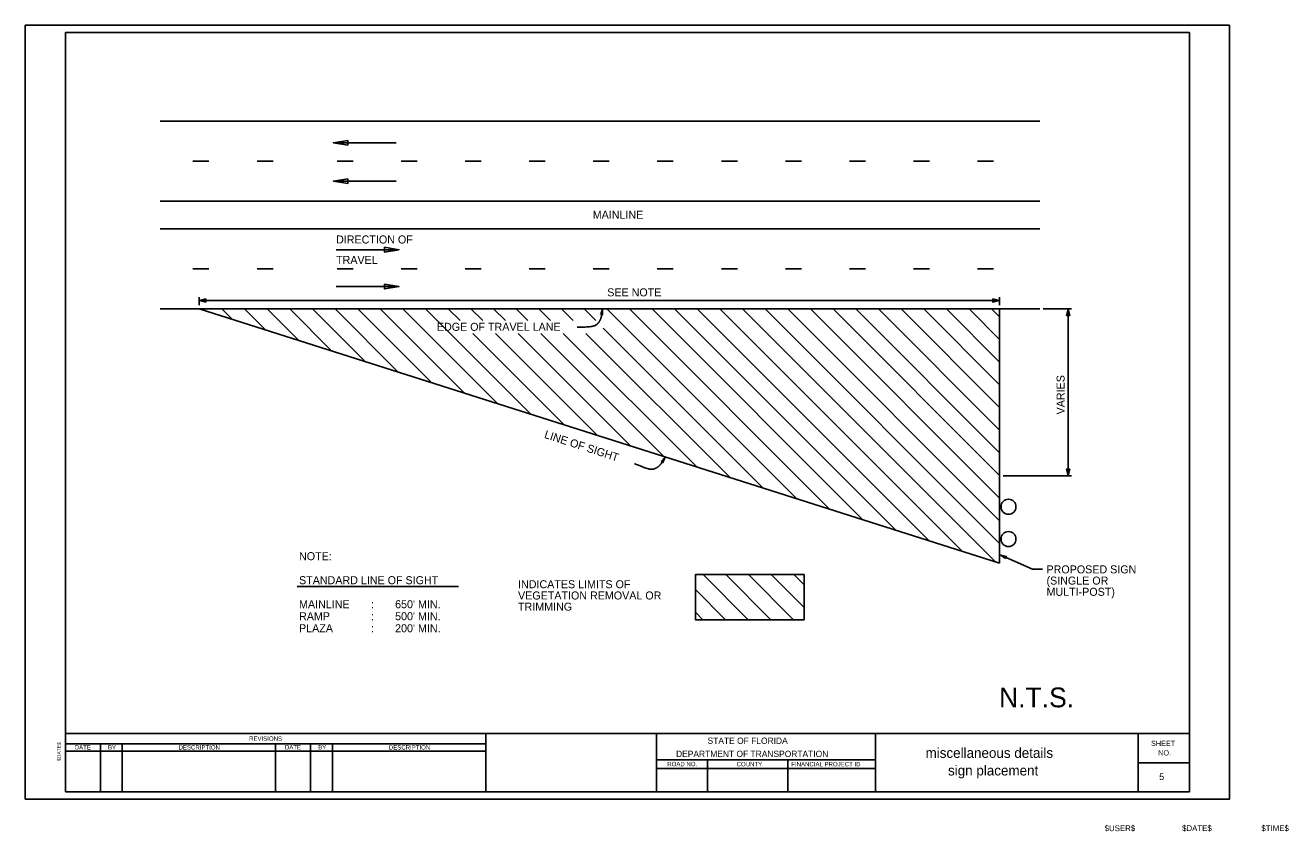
# Model space of a CAD drawing. Extents: x 17890628 to 17891356, y 17896675 to 17897992.
# Drawn here: x 17890644 to 17891356, y 17896675 to 17897130 of the extents above; entities that cross this region are included whole.
import ezdxf

# ---------------------------------------------------------------- set-up
doc = ezdxf.new("R2010")
doc.units = 0
for name, color, linetype in [('Default', 7, 'Continuous'), ('DimLines_dp', 7, 'Continuous'), ('LeaderLine_dp', 7, 'Continuous'), ('PlotBorder_dp', 7, 'Continuous'), ('ScratchEle_dp', 7, 'Continuous'), ('SheetBorder_dp', 7, 'Continuous'), ('SheetLines_dp', 7, 'Continuous'), ('TextLabel', 7, 'Continuous'), ('TextMinor', 7, 'Continuous'), ('TextMisc', 7, 'Continuous')]:
    doc.layers.add(name, color=color, linetype=linetype)

msp = doc.modelspace()

# ---------------------------------------------------------------- linework, layer by layer
at = {"layer": 'Default'}
for p, q in [((17890719.8, 17897075.52), (17891216.02, 17897075.52)), ((17890738.25, 17897052.94), (17890747.28, 17897052.94)), ((17890774.38, 17897052.94), (17890783.41, 17897052.94)), ((17890819.54, 17897052.94), (17890828.57, 17897052.94)), ((17890855.67, 17897052.94), (17890864.7, 17897052.94)), ((17890891.8, 17897052.94), (17890900.83, 17897052.94)), ((17890927.93, 17897052.94), (17890936.96, 17897052.94)), ((17890964.06, 17897052.94), (17890973.09, 17897052.94)), ((17891000.19, 17897052.94), (17891009.22, 17897052.94)), ((17891036.32, 17897052.94), (17891045.35, 17897052.94)), ((17891072.44, 17897052.94), (17891081.48, 17897052.94)), ((17891108.57, 17897052.94), (17891117.61, 17897052.94)), ((17891144.7, 17897052.94), (17891153.73, 17897052.94)), ((17891180.83, 17897052.94), (17891189.86, 17897052.94)), ((17890719.8, 17897030.36), (17891216.02, 17897030.36)), ((17890719.8, 17897014.78), (17891216.02, 17897014.78)), ((17890738.25, 17896992.2), (17890747.28, 17896992.2)), ((17890774.38, 17896992.2), (17890783.41, 17896992.2)), ((17890819.54, 17896992.2), (17890828.57, 17896992.2)), ((17890855.67, 17896992.2), (17890864.7, 17896992.2)), ((17890891.8, 17896992.2), (17890900.83, 17896992.2)), ((17890927.93, 17896992.2), (17890936.96, 17896992.2)), ((17890964.06, 17896992.2), (17890973.09, 17896992.2)), ((17891000.19, 17896992.2), (17891009.22, 17896992.2)), ((17891036.32, 17896992.2), (17891045.35, 17896992.2)), ((17891072.44, 17896992.2), (17891081.48, 17896992.2)), ((17891108.57, 17896992.2), (17891117.61, 17896992.2)), ((17891144.7, 17896992.2), (17891153.73, 17896992.2)), ((17891180.83, 17896992.2), (17891189.86, 17896992.2)), ((17890741.72, 17896971.62), (17890741.72, 17896976.11)), ((17891193.33, 17896971.62), (17891193.33, 17896976.11)), ((17890719.8, 17896969.62), (17891216.02, 17896969.62)), ((17891193.33, 17896974.23), (17890741.72, 17896974.23)), ((17891193.33, 17896826.19), (17890741.72, 17896969.62)), ((17890741.75, 17896969.61), (17890741.74, 17896969.62)), ((17890760.47, 17896963.66), (17890754.51, 17896969.62)), ((17890779.19, 17896957.72), (17890767.29, 17896969.62)), ((17890797.9, 17896951.78), (17890780.06, 17896969.62)), ((17890816.62, 17896945.83), (17890792.84, 17896969.62)), ((17890835.34, 17896939.89), (17890805.61, 17896969.62)), ((17890854.06, 17896933.94), (17890818.38, 17896969.62)), ((17890872.78, 17896928), (17890831.16, 17896969.62)), ((17890891.49, 17896922.05), (17890843.93, 17896969.62)), ((17890910.21, 17896916.11), (17890856.7, 17896969.62)), ((17890928.93, 17896910.16), (17890869.48, 17896969.62)), ((17890888.92, 17896962.95), (17890882.25, 17896969.62)), ((17890901.69, 17896962.95), (17890895.02, 17896969.62)), ((17890914.47, 17896962.95), (17890907.8, 17896969.62)), ((17890927.24, 17896962.95), (17890920.57, 17896969.62)), ((17890940.01, 17896962.95), (17890933.34, 17896969.62)), ((17890952.79, 17896962.95), (17890946.12, 17896969.62)), ((17890965.56, 17896962.95), (17890958.89, 17896969.62)), ((17891078.68, 17896862.61), (17890971.66, 17896969.62)), ((17891097.4, 17896856.66), (17890984.44, 17896969.62)), ((17891116.11, 17896850.72), (17890997.21, 17896969.62)), ((17891134.83, 17896844.77), (17891009.98, 17896969.62)), ((17891153.55, 17896838.83), (17891022.76, 17896969.62)), ((17891172.27, 17896832.88), (17891035.53, 17896969.62)), ((17891190.99, 17896826.94), (17891048.3, 17896969.62)), ((17891193.33, 17896837.36), (17891061.08, 17896969.62)), ((17891193.33, 17896850.14), (17891073.85, 17896969.62)), ((17891193.33, 17896862.91), (17891086.63, 17896969.62)), ((17891193.33, 17896875.68), (17891099.4, 17896969.62)), ((17891193.33, 17896888.46), (17891112.17, 17896969.62)), ((17891193.33, 17896901.23), (17891124.95, 17896969.62)), ((17891193.33, 17896914), (17891137.72, 17896969.62)), ((17891193.33, 17896926.78), (17891150.49, 17896969.62)), ((17891193.33, 17896939.55), (17891163.27, 17896969.62)), ((17891193.33, 17896952.32), (17891176.04, 17896969.62)), ((17891193.33, 17896965.1), (17891188.81, 17896969.62)), ((17891193.33, 17896875.36), (17891193.33, 17896969.62)), ((17891217.91, 17896969.62), (17891233.8, 17896969.62)), ((17890947.65, 17896904.22), (17890896.09, 17896955.78)), ((17890966.37, 17896898.27), (17890908.86, 17896955.78)), ((17890985.09, 17896892.33), (17890921.64, 17896955.78)), ((17891003.8, 17896886.38), (17890934.41, 17896955.78)), ((17891022.52, 17896880.44), (17890947.18, 17896955.78)), ((17891041.24, 17896874.49), (17890959.96, 17896955.78)), ((17891059.96, 17896868.55), (17890969.73, 17896958.78)), ((17891193.33, 17896875.36), (17891193.33, 17896826.19)), ((17891051.51, 17896794.31), (17891026.09, 17896819.73)), ((17891064.28, 17896794.31), (17891038.86, 17896819.73)), ((17891077.06, 17896794.31), (17891051.64, 17896819.73)), ((17891083.02, 17896801.12), (17891064.41, 17896819.73)), ((17891083.02, 17896813.9), (17891077.18, 17896819.73)), ((17891038.73, 17896794.31), (17891021.68, 17896811.37)), ((17891025.96, 17896794.31), (17891021.68, 17896798.6))]:
    msp.add_line(p, q, dxfattribs=at)
for points in [[(17890745.48, 17896973.29), (17890741.72, 17896974.23), (17890745.48, 17896975.17)], [(17891189.57, 17896975.17), (17891193.33, 17896974.23), (17891189.57, 17896973.29)], [(17891002.46, 17896883.51), (17891003.38, 17896882.94), (17891004.62, 17896886)], [(17891083.02, 17896819.73), (17891021.68, 17896819.73), (17891021.68, 17896794.31), (17891083.02, 17896794.31)]]:
    msp.add_lwpolyline(points, close=True, dxfattribs=at)
for centre in [(17891198.32, 17896857.99), (17891198.32, 17896839.79)]:
    msp.add_circle(centre, 4.21, dxfattribs=at)
msp.add_open_spline([(17890987.39, 17896882.36), (17890995.04, 17896878.92), (17890999.26, 17896879.34), (17891002.68, 17896882.29), (17891004.52, 17896885.88)], degree=2, dxfattribs=at)
at = {"layer": 'DimLines_dp'}
msp.add_line((17891231.91, 17896969.62), (17891231.91, 17896875.36), dxfattribs=at)
at = {"layer": 'LeaderLine_dp'}
for p, q in [((17890852.86, 17897063.29), (17890817.45, 17897063.29)), ((17890852.86, 17897041.65), (17890817.45, 17897041.65)), ((17890818.97, 17897002.96), (17890854.38, 17897002.96)), ((17890818.97, 17896982.17), (17890854.38, 17896982.17)), ((17891195.22, 17896875.36), (17891233.8, 17896875.36)), ((17891211.78, 17896822.83), (17891193.93, 17896830.71)), ((17891217.5, 17896822.83), (17891211.78, 17896822.83))]:
    msp.add_line(p, q, dxfattribs=at)
for points in [[(17890825.58, 17897064.64), (17890825.58, 17897061.93), (17890817.45, 17897063.29)], [(17890825.58, 17897043.01), (17890825.58, 17897040.3), (17890817.45, 17897041.65)], [(17890846.25, 17897004.32), (17890846.25, 17897001.61), (17890854.38, 17897002.96)], [(17890846.25, 17896983.52), (17890846.25, 17896980.81), (17890854.38, 17896982.17)], [(17890968.27, 17896966.47), (17890969.34, 17896966.33), (17890969.22, 17896969.62)], [(17891230.97, 17896965.86), (17891231.91, 17896969.62), (17891232.86, 17896965.86)], [(17891232.86, 17896879.12), (17891231.91, 17896875.36), (17891230.97, 17896879.12)], [(17891196.68, 17896828.9), (17891197.12, 17896829.89), (17891193.93, 17896830.71)]]:
    msp.add_lwpolyline(points, close=True, dxfattribs=at)
msp.add_open_spline([(17890955, 17896959.24), (17890963.38, 17896959.24), (17890967.06, 17896961.36), (17890968.97, 17896965.45), (17890969.18, 17896969.47)], degree=2, dxfattribs=at)
at = {"layer": 'PlotBorder_dp'}
msp.add_lwpolyline([(17890643.63, 17896693.1), (17891322.99, 17896693.1), (17891322.99, 17897129.53), (17890643.63, 17897129.53)], close=True, dxfattribs=at)
at = {"layer": 'ScratchEle_dp'}
msp.add_line((17890796.99, 17896812.99), (17890888.02, 17896812.99), dxfattribs=at)
at = {"layer": 'SheetBorder_dp'}
for p, q in [((17890666.28, 17897125.41), (17890666.28, 17896697.21)), ((17890666.28, 17897125.41), (17891300.34, 17897125.41)), ((17891300.34, 17897125.41), (17891300.34, 17896697.21)), ((17890666.28, 17896730.15), (17891300.34, 17896730.15)), ((17890666.28, 17896697.21), (17891300.34, 17896697.21))]:
    msp.add_line(p, q, dxfattribs=at)
at = {"layer": 'SheetLines_dp'}
for p, q in [((17890903.43, 17896730.15), (17890903.43, 17896697.21)), ((17890999.78, 17896730.15), (17890999.78, 17896697.21)), ((17891123.3, 17896697.21), (17891123.3, 17896730.15)), ((17891271.52, 17896697.21), (17891271.52, 17896730.15)), ((17890666.28, 17896724.39), (17890903.43, 17896724.39)), ((17890666.28, 17896720.27), (17890903.43, 17896720.27)), ((17890686.04, 17896724.39), (17890686.04, 17896697.21)), ((17890698.39, 17896724.39), (17890698.39, 17896697.21)), ((17890784.86, 17896724.39), (17890784.86, 17896697.21)), ((17890804.62, 17896724.39), (17890804.62, 17896697.21)), ((17890816.97, 17896724.39), (17890816.97, 17896697.21)), ((17890999.78, 17896715.33), (17891123.3, 17896715.33)), ((17891028.6, 17896715.33), (17891028.6, 17896697.21)), ((17891073.89, 17896715.33), (17891073.89, 17896697.21)), ((17891271.52, 17896713.68), (17891300.34, 17896713.68)), ((17890999.78, 17896710.39), (17891123.3, 17896710.39))]:
    msp.add_line(p, q, dxfattribs=at)

# ---------------------------------------------------------------- texts
at = {"layer": 'Default'}
msp.add_text('N.T.S.', height=11.167, rotation=360, dxfattribs=at).set_placement((17891193.01, 17896744.91))
at = {"layer": 'TextLabel'}
for s, height, p in [('MAINLINE', 4.516, (17890963.78, 17897020.38)), ('DIRECTION OF', 4.5161, (17890818.97, 17897006.47)), ('TRAVEL', 4.516, (17890818.97, 17896994.95)), ('SEE NOTE', 4.516, (17890971.96, 17896976.65)), ('EDGE OF TRAVEL LANE', 4.5161, (17890875.84, 17896957.23)), ('NOTE:', 4.516, (17890798.09, 17896827.88)), ('STANDARD LINE OF SIGHT', 4.5161, (17890798.09, 17896814.33)), ('(SINGLE OR', 4.516, (17891219.76, 17896814.11)), ('PROPOSED SIGN', 4.5161, (17891219.76, 17896820.43)), ('INDICATES LIMITS OF', 4.5161, (17890921.63, 17896812.05)), ('MULTI-POST)', 4.5161, (17891219.76, 17896807.79)), ('MAINLINE', 4.516, (17890798.09, 17896800.78)), (':', 4.52, (17890838.73, 17896800.78)), ("650' MIN.", 4.516, (17890852.28, 17896800.78)), ('VEGETATION REMOVAL OR', 4.5161, (17890921.63, 17896805.72)), ('RAMP', 4.516, (17890798.09, 17896794.01)), (':', 4.52, (17890838.73, 17896794.01)), ("500' MIN.", 4.516, (17890852.28, 17896794.01)), ('TRIMMING', 4.516, (17890921.63, 17896799.4)), ('PLAZA', 4.516, (17890798.09, 17896787.23)), (':', 4.52, (17890838.73, 17896787.23)), ("200' MIN.", 4.516, (17890852.28, 17896787.23))]:
    msp.add_text(s, height=height, dxfattribs=at).set_placement(p)
for s, height, rotation, p in [('VARIES', 4.516, 90, (17891229.97, 17896910.08)), ('LINE OF SIGHT', 4.5161, 341.99999, (17890936.07, 17896896.94))]:
    msp.add_text(s, height=height, rotation=rotation, dxfattribs=at).set_placement(p)
at = {"layer": 'TextMinor'}
msp.add_text('$DATE$', height=2.018, rotation=90, dxfattribs=at).set_placement((17890663.68, 17896714.68))
at = {"layer": 'TextMisc'}
for s, height, p in [('REVISIONS', 2.47, (17890769.91, 17896726.03)), ('STATE OF FLORIDA', 3.5573, (17891028.56, 17896724.29)), ('BY', 2.47, (17890690.28, 17896721.13)), ('BY', 2.47, (17890808.86, 17896721.13)), ('DEPARTMENT OF TRANSPORTATION', 3.5573, (17891010.76, 17896716.86)), ('miscellaneous details', 5.6592, (17891151.54, 17896716.39)), ('ROAD NO.', 2.47, (17891005.83, 17896711.67)), ('COUNTY', 2.47, (17891044.95, 17896711.62)), ('FINANCIAL PROJECT ID', 2.4704, (17891075.78, 17896711.62)), ('sign placement', 5.6592, (17891164.2, 17896706.48)), ('5', 3.77, (17891283.34, 17896703.91)), ('$USER$', 3.312, (17891252.55, 17896675.08)), ('$DATE$', 3.312, (17891296.25, 17896675.08)), ('$TIME$', 3.312, (17891340.98, 17896675.08))]:
    msp.add_text(s, height=height, dxfattribs=at).set_placement(p)
for s, height, rotation, p in [('SHEET', 2.964, 359.86066, (17891278.72, 17896723.11)), ('DATE', 2.47, 359.86925, (17890671.51, 17896721.13)), ('DESCRIPTION', 2.4699, 0.04975, (17890730.14, 17896721.09)), ('DATE', 2.47, 359.86925, (17890790.09, 17896721.18)), ('DESCRIPTION', 2.4699, 0.04975, (17890848.76, 17896721.09)), ('NO.', 2.964, 359.86066, (17891282.76, 17896717.76))]:
    msp.add_text(s, height=height, rotation=rotation, dxfattribs=at).set_placement(p)

doc.saveas('drawing.dxf')
